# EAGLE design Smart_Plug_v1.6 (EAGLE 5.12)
DIGIKEY: P1.2GCT-ND; HEYCO: 5940; NEWARK: FA-20H, 40MHZ, 10PPM, 12PF; TI: CustomTrans

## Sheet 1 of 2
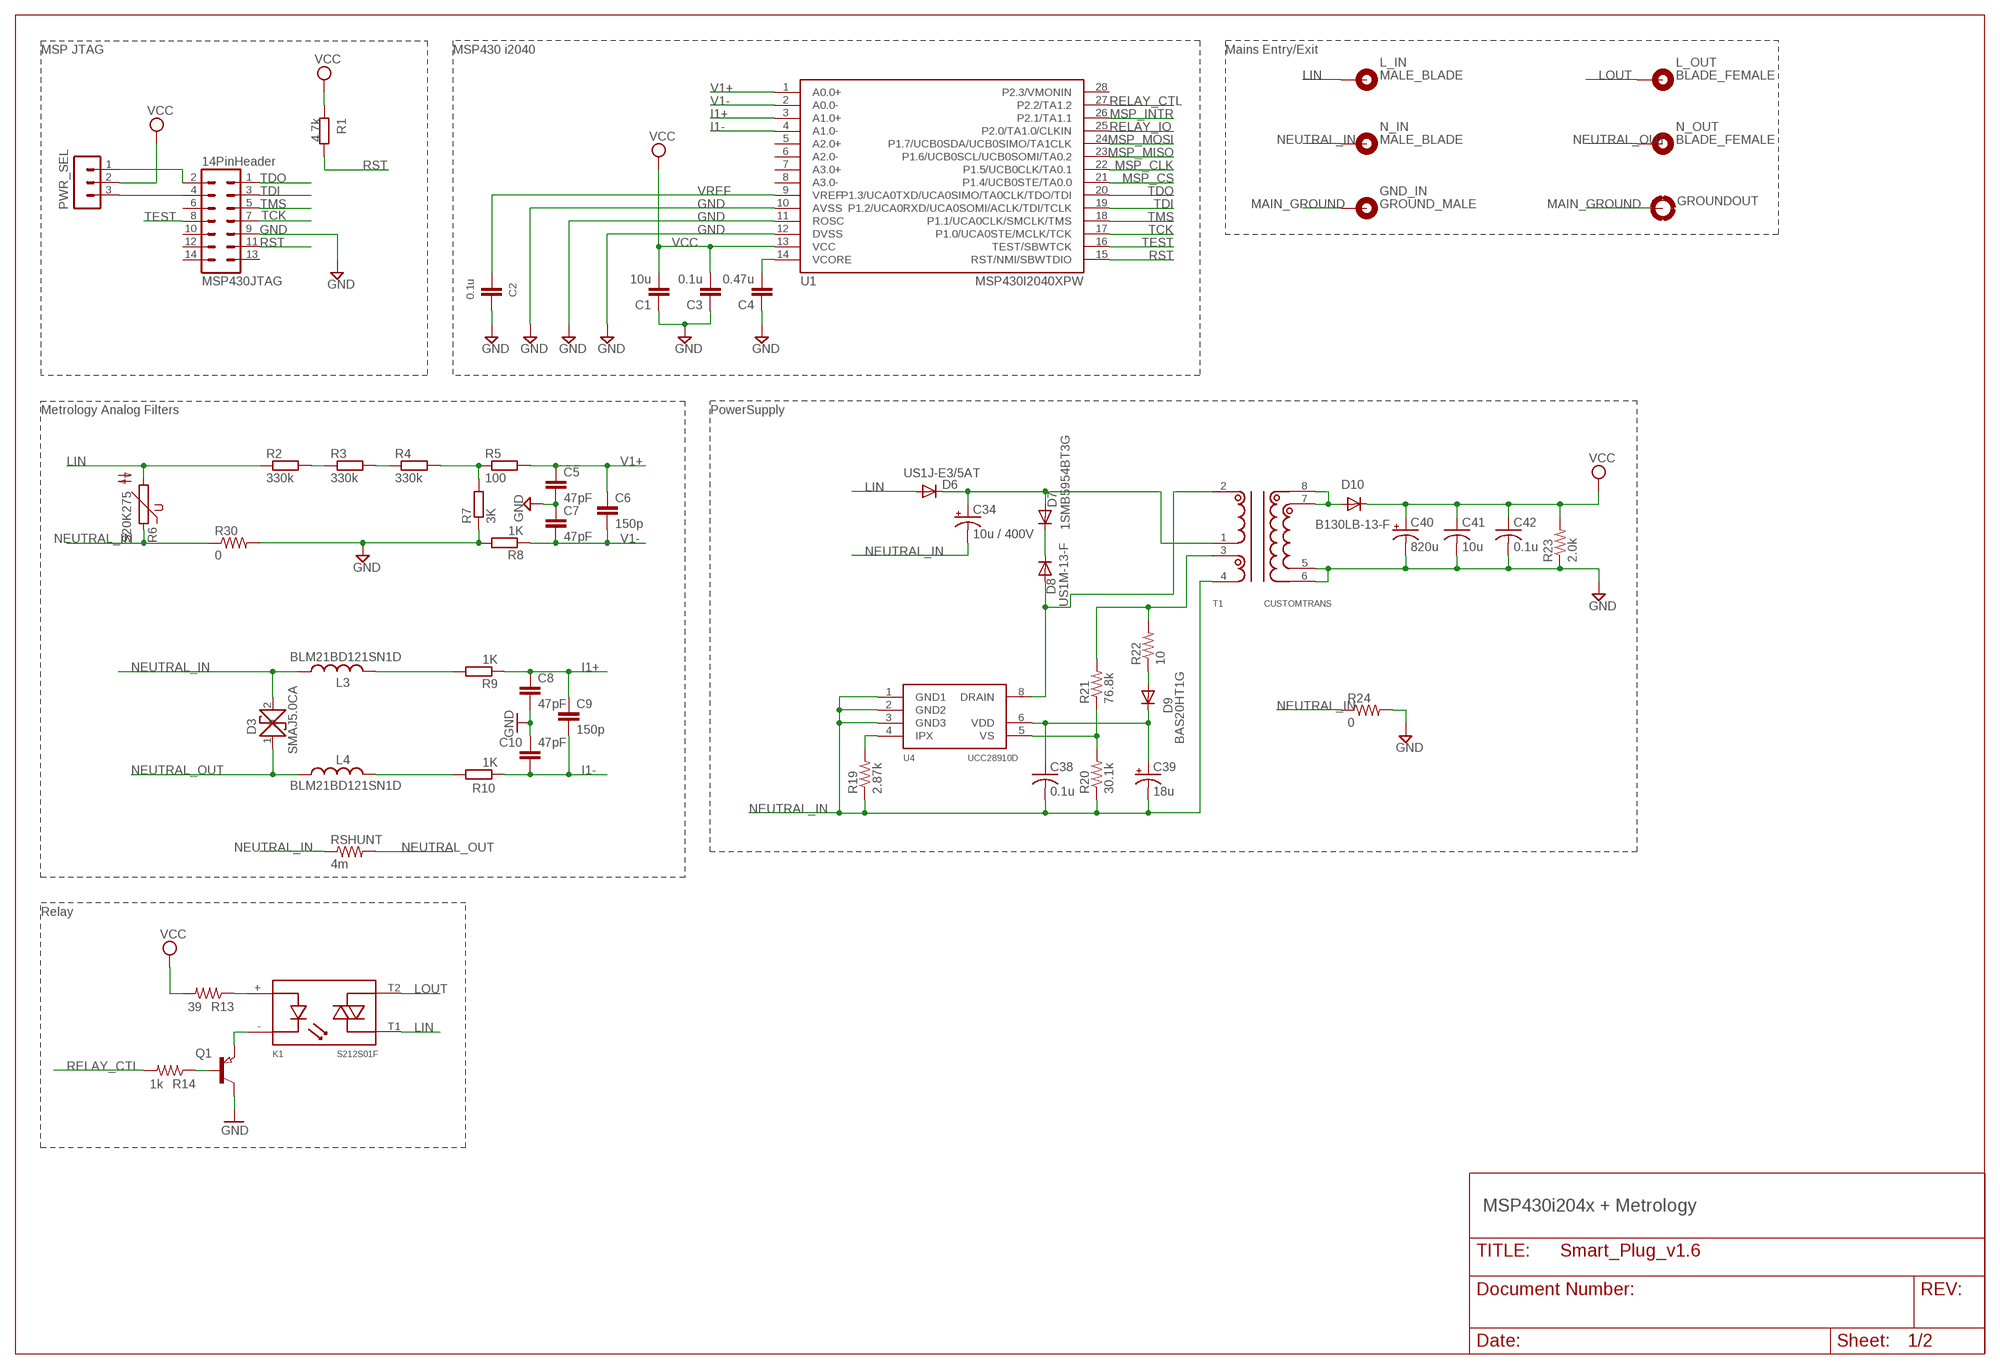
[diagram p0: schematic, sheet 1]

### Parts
C1  10u  C-EUC0603  [C0603]
C2  0.1u  C-EUC0603  [C0603]
C3  0.1u  C-EUC0603  [C0603]
C4  0.47u  C-EUC0603  [C0603]
C5  47pF  C-EUC0603  [C0603]
C6  150p  C-EUC0603  [C0603]
C7  47pF  C-EUC0603  [C0603]
C8  47pF  C-EUC0603  [C0603]
C9  150p  C-EUC0603  [C0603]
C10  47pF  C-EUC0603  [C0603]
C34  10u / 400V  CPOL-USE5-10.5  [E5-10,5]
C38  0.1u  C-USC0603  [C0603]
C39  18u  CPOL-USE5-5  [E5-5]
C40  820u  CPOL-USE3.5-8  [E3,5-8]
C41  10u  C-USC1210  [C1210]
C42  0.1u  C-USC0805  [C0805]
D3  SMAJ5.0CA  SMAJ  [DO-214]
D6  US1J-E3/5AT  DIODE-DO-214AC  [DO-214AC]
D7  1SMB5954BT3G  DIODE-DO-214AC  [DO-214AC]
D8  US1M-13-F  DIODE-DO-214AC  [DO-214AC]
D9  BAS20HT1G  DIODE-SOD323-R  [SOD323-R]
D10  B130LB-13-F  DIODE-DO214AA  [DO214AA]
GND_IN  GROUND_MALE  [GROUND_MALE]
GROUNDOUT  MOUNT-PAD-ROUND3.0  [3,0-PAD]
K1  S212S01F  [S212S01]
L3  BLM21BD121SN1D  L-USL2012C  [L2012C]
L4  BLM21BD121SN1D  L-USL2012C  [L2012C]
L_IN  MALE_BLADE  [BLADE_MALE]
L_OUT  BLADE_FEMALE  [BLADE_FEMALE]
MSP430JTAG  14PinHeader  MA07-2  [MA07-2]
N_IN  MALE_BLADE  [BLADE_MALE]
N_OUT  BLADE_FEMALE  [BLADE_FEMALE]
PWR_SEL  MA03-1MA03-1  [MA03-1]
Q1  PNP-TRANSISTOR_SOT23  [SOT23]
R1  4.7k  R-EU_R0603  [R0603]
R2  330k  R-EU_R0603  [R0603]
R3  330k  R-EU_R0603  [R0603]
R4  330k  R-EU_R0603  [R0603]
R5  100  R-EU_R0603  [R0603]
R6  S20K275  [S20K275]
R7  3K  R-EU_R0603  [R0603]
R8  1K  R-EU_R0603  [R0603]
R9  1K  R-EU_R0603  [R0603]
R10  1K  R-EU_R0603  [R0603]
R13  39  R-US_R0603  [R0603]
R14  1k  R-US_R0603  [R0603]
R19  2.87k  R-US_R0603  [R0603]
R20  30.1k  R-US_R0603  [R0603]
R21  76.8k  R-US_R0603  [R0603]
R22  10  R-US_R0603  [R0603]
R23  2.0k  R-US_R0603  [R0603]
R24  0  R-US_R0805  [R0805]
R30  0  R-US_R0603  [R0603]
RSHUNT  4m  R-US_R4527  [R4527]
T1  CUSTOMTRANS  [TRANS]
U1  MSP430I2040XPW  [TSSOP28]
U4  UCC28910D  [SOIC(D)]

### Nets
DVCC: MSP430JTAG.2 PWR_SEL.1
GND: C1.1 C2.2 C3.1 C4.1 C5.2 C7.1 C8.2 C10.1 C40.- C41.2 C42.2 MSP430JTAG.9 Q1.3(C) R7.1 R8.2 R23.1 R24.2 R30.2 T1.5 T1.6 U1.10(AVSS) U1.11(ROSC) U1.12(DVSS) ; also sheet 2
I1+: C8.1 C9.1 R9.1 U1.3(A1.0+)
I1-: C9.2 C10.2 R10.1 U1.4(A1.0-)
LIN: D6.A K1.T1 L_IN.P$3 R2.1 R6.2
LOUT: K1.T2 L_OUT.P$1
MAIN_GROUND: GND_IN.P$1 GROUNDOUT.B3,0(MOUNT)
MSP_CLK: U1.22(P1.5/UCB0CLK/TA0.1) ; also sheet 2
MSP_CS: U1.21(P1.4/UCB0STE/TA0.0) ; also sheet 2
MSP_INTR: U1.26(P2.1/TA1.1) ; also sheet 2
MSP_MISO: U1.23(P1.6/UCB0SCL/UCB0SOMI/TA0.2) ; also sheet 2
MSP_MOSI: U1.24(P1.7/UCB0SDA/UCB0SIMO/TA1CLK) ; also sheet 2
N$3: L4.2 R10.2
N$4: C34.+ D6.C D7.A T1.1
N$9: K1.+ R13.1
N$10: K1.- Q1.2(E)
N$13: Q1.1(B) R14.1
N$17: D7.C D8.C
N$18: D10.A T1.7 T1.8
N$21: R19.2 U4.4(IPX)
N$22: D8.A T1.2 U4.8(DRAIN)
N$23: C38.1 C39.+ D9.C U4.6(VDD)
N$24: R20.2 R21.1 U4.5(VS)
N$25: D9.A R22.1
N$26: R21.2 R22.2 T1.3
N$32: R4.2 R5.1 R7.2
N$35: C4.2 U1.14(VCORE)
N$39: R2.2 R3.1
N$42: L3.2 R9.2
N$130: MSP430JTAG.4 PWR_SEL.3
NEUTRAL_IN: C34.- C38.2 C39.- D3.2 L3.1 N_IN.P$3 R6.1 R19.1 R20.1 R24.1 R30.1 RSHUNT.1 T1.4 U4.1(GND1) U4.2(GND2) U4.3(GND3)
NEUTRAL_OUT: D3.1 L4.1 N_OUT.P$1 RSHUNT.2
RELAY_CTL: R14.2 U1.27(P2.2/TA1.2)
RELAY_IO: U1.25(P2.0/TA1.0/CLKIN) ; also sheet 2
RST: MSP430JTAG.11 R1.2 U1.15(RST/NMI/SBWTDIO)
TCK: MSP430JTAG.7 U1.17(P1.0/UCA0STE/MCLK/TCK)
TDI: MSP430JTAG.3 U1.19(P1.2/UCA0RXD/UCA0SOMI/ACLK/TDI/TCLK)
TDO: MSP430JTAG.1 U1.20(P1.3/UCA0TXD/UCA0SIMO/TA0CLK/TDO/TDI)
TEST: MSP430JTAG.8 U1.16(TEST/SBWTCK)
TMS: MSP430JTAG.5 U1.18(P1.1/UCA0CLK/SMCLK/TMS)
V1: R3.2 R4.1
V1+: C5.1 C6.1 R5.2 U1.1(A0.0+)
V1-: C6.2 C7.2 R8.1 U1.2(A0.0-)
VCC: C1.2 C3.2 C40.+ C41.1 C42.1 D10.C PWR_SEL.2 R1.1 R13.2 R23.2 U1.13(VCC) ; also sheet 2
VREF: C2.1 U1.9(VREF)
Unconnected: MSP430JTAG.6 MSP430JTAG.10 MSP430JTAG.12 MSP430JTAG.13 MSP430JTAG.14 U1.5(A2.0+) U1.6(A2.0-) U1.7(A3.0+) U1.8(A3.0-) U1.28(P2.3/VMONIN)

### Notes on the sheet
- MSP JTAG | MSP430 i2040 | Mains Entry/Exit
- Metrology Analog Filters | PowerSupply
- Relay
- MSP430i204x + Metrology

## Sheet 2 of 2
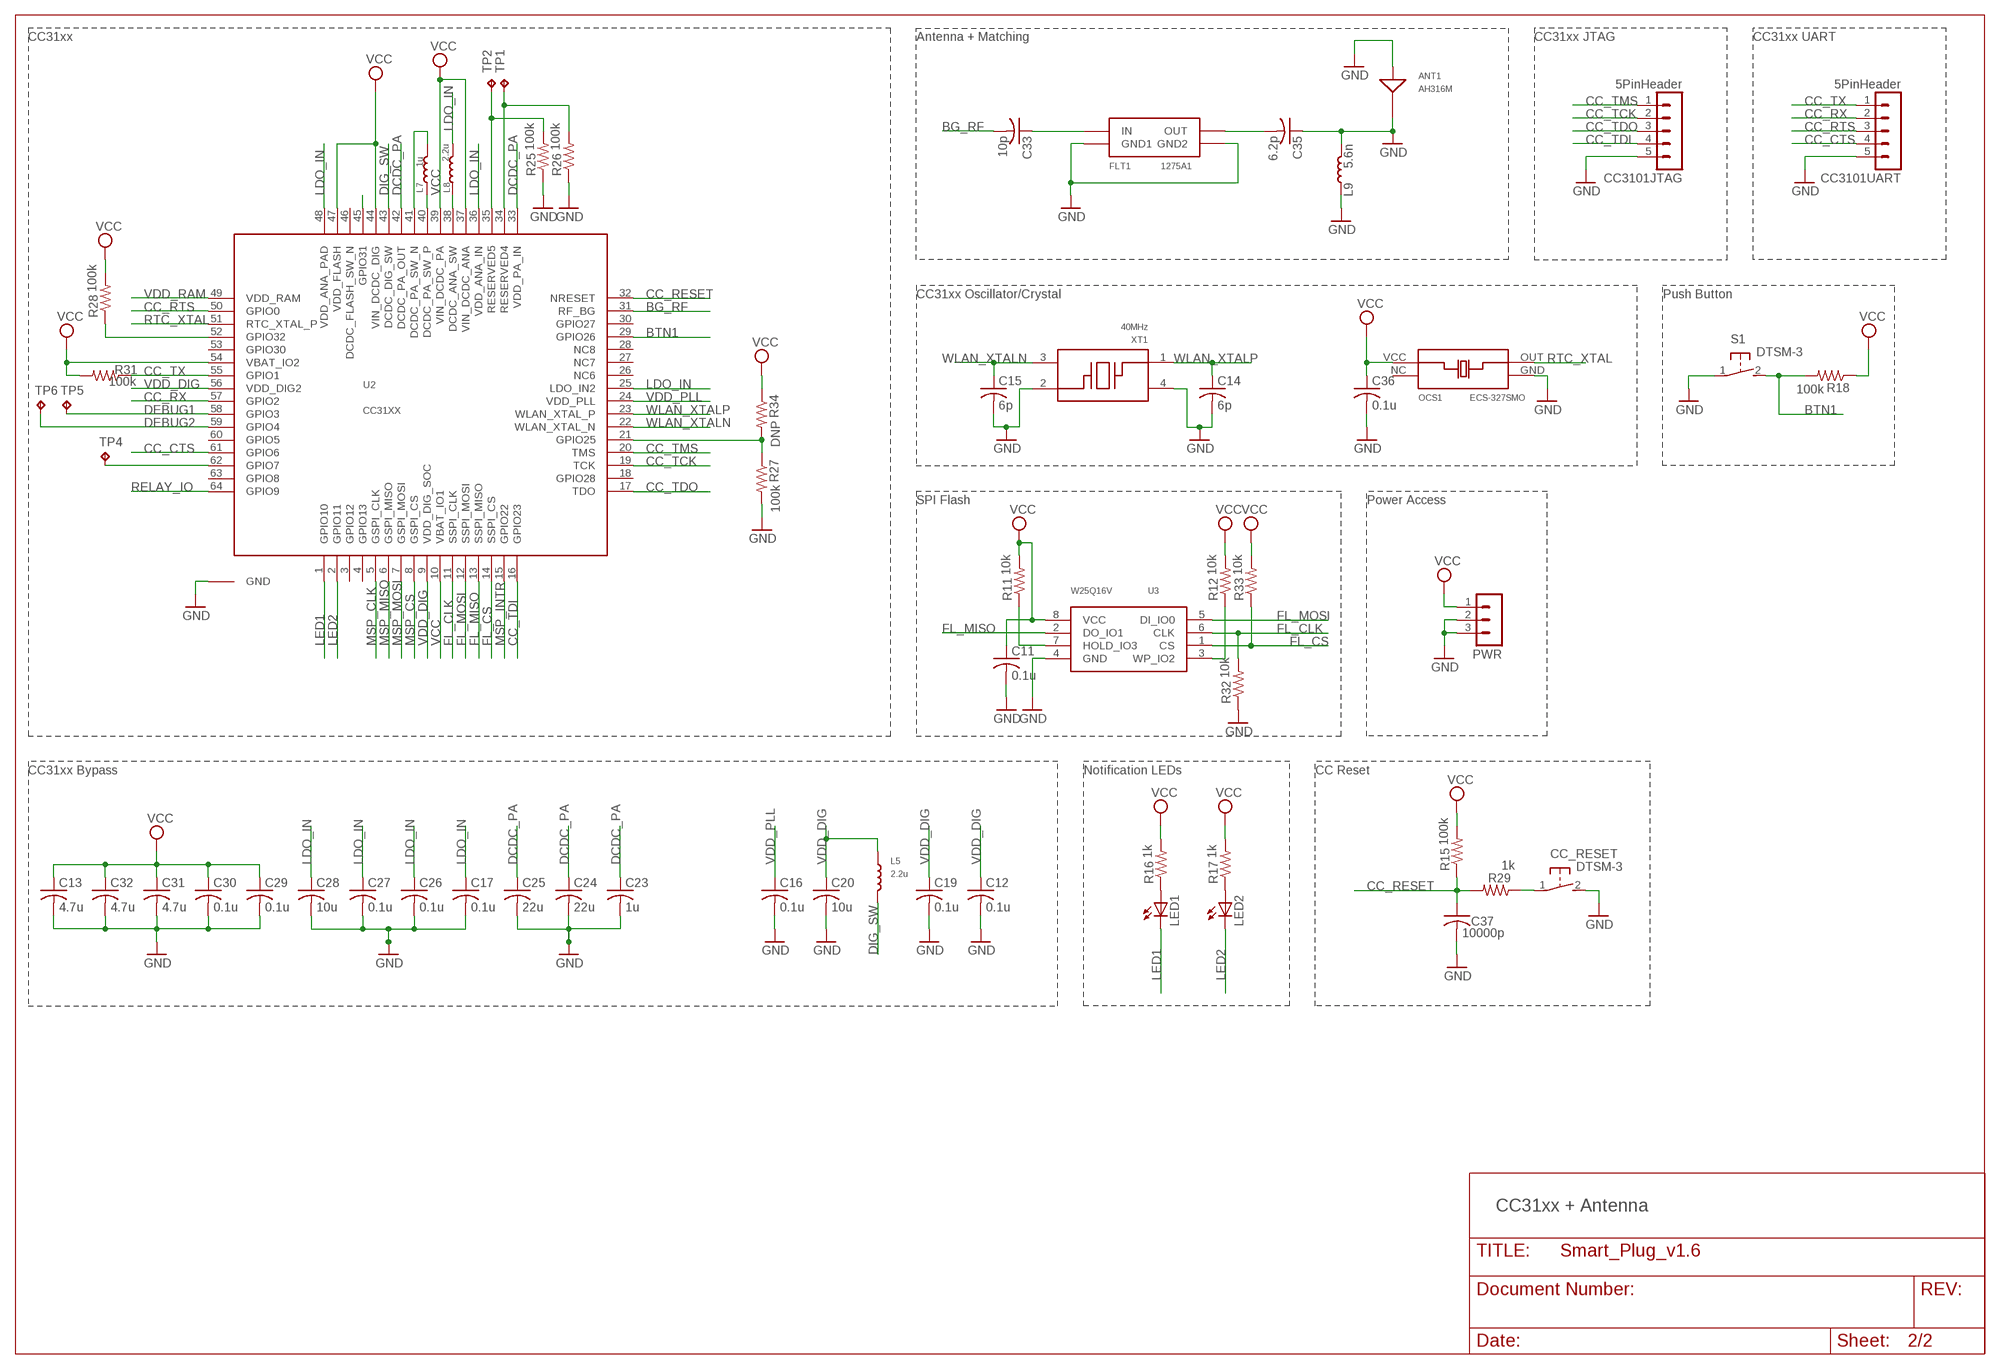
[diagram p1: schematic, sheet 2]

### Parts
ANT1  AH316M  [AH316M]
C11  0.1u  C-USC0402  [C0402]
C12  0.1u  C-USC0201  [C0201]
C13  4.7u  C-USC0402  [C0402]
C14  6p  C-USC0402  [C0402]
C15  6p  C-USC0402  [C0402]
C16  0.1u  C-USC0201  [C0201]
C17  0.1u  C-USC0201  [C0201]
C19  0.1u  C-USC0201  [C0201]
C20  10u  C-USC0402  [C0402]
C23  1u  C-USC0201  [C0201]
C24  22u  C-USC0603  [C0603]
C25  22u  C-USC0603  [C0603]
C26  0.1u  C-USC0201  [C0201]
C27  0.1u  C-USC0402  [C0402]
C28  10u  C-USC0402  [C0402]
C29  0.1u  C-USC0201  [C0201]
C30  0.1u  C-USC0201  [C0201]
C31  4.7u  C-USC0402  [C0402]
C32  4.7u  C-USC0402  [C0402]
C33  10p  C-USC0201  [C0201]
C35  6.2p  C-USC0201  [C0201]
C36  0.1u  C-USC0402  [C0402]
C37  10000p  C-USC0201  [C0201]
CC3101JTAG  5PinHeader  MA05-1  [MA05-1]
CC3101UART  5PinHeader  MA05-1  [MA05-1]
CC_RESET  DTSM-3  [DTSM-3]
FLT1  1275A1  [1275A1]
L5  2.2u  LQM2MPN2R2MG0  [2016]
L7  1u  LQM2HPN1R0MJC  [2520]
L8  2.2u  LQM2MPN2R2MG0  [2016]
L9  5.6n  LQM2HPN1R0MJCL0201  [L0201]
LED1  LEDCHIP-LED0603  [CHIP-LED0603]
LED2  LEDCHIP-LED0603  [CHIP-LED0603]
OCS1  ECS-327SMO  [ECS-327SMO]
PWR  MA03-1  [MA03-1]
R11  10k  R-US_R0402  [R0402]
R12  10k  R-US_R0402  [R0402]
R15  100k  R-US_R0201  [R0201]
R16  1k  R-US_R0402  [R0402]
R17  1k  R-US_R0402  [R0402]
R18  100k  R-US_R0201  [R0201]
R25  100k  R-US_R0201  [R0201]
R26  100k  R-US_R0201  [R0201]
R27  100k  R-US_R0201  [R0201]
R28  100k  R-US_R0201  [R0201]
R29  1k  R-US_R0201  [R0201]
R31  100k  R-US_R0201  [R0201]
R32  10k  R-US_R0201  [R0201]
R33  10k  R-US_R0201  [R0201]
R34  DNP  R-US_R0201  [R0201]
S1  DTSM-3  [DTSM-3]
TP1  TPTP06R  [TP06R]
TP2  TPTP06R  [TP06R]
TP4  TPTP06R  [TP06R]
TP5  TPTP06R  [TP06R]
TP6  TPTP06R  [TP06R]
U2  CC31XX  [S-PVQFN-N64]
U3  W25Q16V  [8PINWSON]
XT1  40MHz  40.0000MF15Z  [FA-20H]

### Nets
ANA2_P: U2.45(GPIO31)
BG_RF: C33.2 U2.31(RF_BG)
BTN1: R18.2 S1.2 U2.29(GPIO26)
CC_CTS: CC3101UART.4 U2.61(GPIO6)
CC_RESET: C37.1 R15.1 R29.2 U2.32(NRESET)
CC_RTS: CC3101UART.3 U2.50(GPIO0)
CC_RX: CC3101UART.2 U2.57(GPIO2)
CC_TCK: CC3101JTAG.2 U2.19(TCK)
CC_TDI: CC3101JTAG.4 U2.16(GPIO23)
CC_TDO: CC3101JTAG.3 U2.17(TDO)
CC_TMS: CC3101JTAG.1 U2.20(TMS)
CC_TX: CC3101UART.1 R31.1 U2.55(GPIO1)
DCDC_PA: C23.1 C24.1 C25.1 U2.33(VDD_PA_IN) U2.42(DCDC_PA_OUT)
DEBUG1: TP5.TP U2.58(GPIO3)
DEBUG2: TP6.TP U2.59(GPIO4)
DIG_SW: L5.P$2 U2.43(DCDC_DIG_SW)
FL_CLK: R32.2 U2.11(SSPI_CLK) U3.6(CLK)
FL_CS: R33.1 U2.14(SSPI_CS) U3.1(CS)
FL_MISO: U2.13(SSPI_MISO) U3.2(DO_IO1)
FL_MOSI: U2.12(SSPI_MOSI) U3.5(DI_IO0)
GND: ANT1.P$1 ANT1.P$2 C11.2 C12.2 C13.2 C14.2 C15.2 C16.2 C17.2 C19.2 C20.2 C23.2 C24.2 C25.2 C26.2 C27.2 C28.2 C29.2 C30.2 C31.2 C32.2 C35.1 C36.2 C37.2 CC3101JTAG.5 CC3101UART.5 CC_RESET.2 FLT1.P$2(GND1) FLT1.P$4(GND2) L9.1 L9.2 OCS1.GND PWR.2 PWR.3 R25.1 R26.1 R27.2 R32.1 S1.1 U2.P$65(GND) U3.4(GND) XT1.2 XT1.4 ; also sheet 1
LDO_IN: C17.1 C26.1 C27.1 C28.1 L8.P$2 U2.25(LDO_IN2) U2.36(VDD_ANA_IN) U2.48(VDD_ANA_PAD)
LED1: LED1.C U2.1(GPIO10)
LED2: LED2.C U2.2(GPIO11)
MSP_CLK: U2.5(GSPI_CLK) ; also sheet 1
MSP_CS: U2.8(GSPI_CS) ; also sheet 1
MSP_INTR: U2.15(GPIO22) ; also sheet 1
MSP_MISO: U2.6(GSPI_MISO) ; also sheet 1
MSP_MOSI: U2.7(GSPI_MOSI) ; also sheet 1
N$1: L7.P$1 U2.40(DCDC_PA_SW_P)
N$2: L7.P$2 U2.41(DCDC_PA_SW_N)
N$5: L8.P$1 U2.38(DCDC_ANA_SW)
N$6: C35.2 FLT1.P$3(OUT)
N$7: R11.1 U3.7(HOLD_IO3)
N$8: R12.1 U3.3(WP_IO2)
N$11: C33.1 FLT1.P$1(IN)
N$12: R25.2 TP2.TP U2.35(RESERVED5)
N$14: R26.2 TP1.TP U2.34(RESERVED4)
N$15: R27.1 R34.2 U2.21(GPIO25)
N$16: TP4.TP U2.62(GPIO7)
N$19: LED1.A R16.1
N$20: LED2.A R17.1
N$30: R28.1 U2.52(GPIO32)
N$31: CC_RESET.1 R29.1
RELAY_IO: U2.64(GPIO9) ; also sheet 1
RTC_XTAL: OCS1.OUT U2.51(RTC_XTAL_P)
VCC: C11.1 C13.1 C29.1 C30.1 C31.1 C32.1 C36.1 OCS1.VCC PWR.1 R11.2 R12.2 R15.2 R16.2 R17.2 R18.1 R28.2 R31.2 R33.2 R34.1 U2.10(VBAT_IO1) U2.37(VIN_DCDC_ANA) U2.39(VIN_DCDC_PA) U2.44(VIN_DCDC_DIG) U2.47(VDD_FLASH) U2.54(VBAT_IO2) U3.8(VCC) ; also sheet 1
VDD_DIG: C12.1 C19.1 C20.1 L5.P$1 U2.9(VDD_DIG_SOC) U2.56(VDD_DIG2)
VDD_PLL: C16.1 U2.24(VDD_PLL)
VDD_RAM: U2.49(VDD_RAM)
WLAN_XTALN: C15.1 U2.22(WLAN_XTAL_N) XT1.3
WLAN_XTALP: C14.1 U2.23(WLAN_XTAL_P) XT1.1
Unconnected: OCS1.NC U2.3(GPIO12) U2.4(GPIO13) U2.18(GPIO28) U2.26(NC6) U2.27(NC7) U2.28(NC8) U2.30(GPIO27) U2.46(DCDC_FLASH_SW_N) U2.53(GPIO30) U2.60(GPIO5) U2.63(GPIO8)

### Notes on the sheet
- CC31xx | Antenna + Matching | CC31xx JTAG | CC31xx UART
- CC31xx Oscillator/Crystal | Push Button
- SPI Flash | Power Access
- CC31xx Bypass | Notification LEDs | CC Reset
- CC31xx + Antenna

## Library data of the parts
ANT1 = Yuden_Ant:AH316M
C1-C7 = resistor:C-EU: CAPACITOR, European symbol
C8-C10 = ElecMeter:C-EU: CAPACITOR, European symbol
C11-C17 C19 C20 C23-C33 C35-C38 C41 C42 = rcl:C-US: CAPACITOR, American symbol
C34 C39 C40 = rcl:CPOL-US: POLARIZED CAPACITOR, American symbol
CC3101JTAG CC3101UART = con-lstb:MA05-1: PIN HEADER; OC_FARNELL: unknown; OC_NEWARK: unknown
CC_RESET S1 = switch-tact:DTSM-3
D3 = CON1:SMAJ
D6-D10 = diode:DIODE-: DIODE
FLT1 = TDK_RF_Filter:1275A1
GND_IN = Heyco_Connectors:GROUND_MALE
GROUNDOUT = holes:MOUNT-PAD-ROUND: MOUNTING PAD, round
K1 = Sharp_SSR:S212S01F
L3 L4 = ElecMeter:L-US: INDUCTOR, American symbol
L5 L8 = MurataInductors:LQM2MPN2R2MG0
L7 L9 = MurataInductors:LQM2HPN1R0MJC
L_IN N_IN = Heyco_Connectors:MALE_BLADE
L_OUT N_OUT = Heyco_Connectors:BLADE_FEMALE
LED1 LED2 = led:LED: LED
MSP430JTAG = partsElecMeter_i4020Mod:MA07-2: PIN HEADER
OCS1 = ECS_OSC:ECS-327SMO
PWR = con-lstb:MA03-1: PIN HEADER; OC_FARNELL: unknown; OC_NEWARK: unknown
PWR_SEL = ElecMeter:MA03-1: PIN HEADER
Q1 = semicon-smd-ipc:PNP-TRANSISTOR_: PNP TRANSISTOR
R1-R5 R7-R10 = ElecMeter:R-EU_: RESISTOR, European symbol
R6 = varistor:S20K275: VARISTOR
R11-R34 RSHUNT = rcl:R-US_: RESISTOR, American symbol
T1 = RencoTransformer:CUSTOMTRANS
TP1 TP2 TP4-TP6 = testpad:TP: Test pad
U1 = MSP430i204x:MSP430I2040XPW
U2 = CC31xx:CC31XX
U3 = W25Q16V:W25Q16V
U4 = UCC28910:UCC28910D
XT1 = Epson Crystals:40.0000MF15Z

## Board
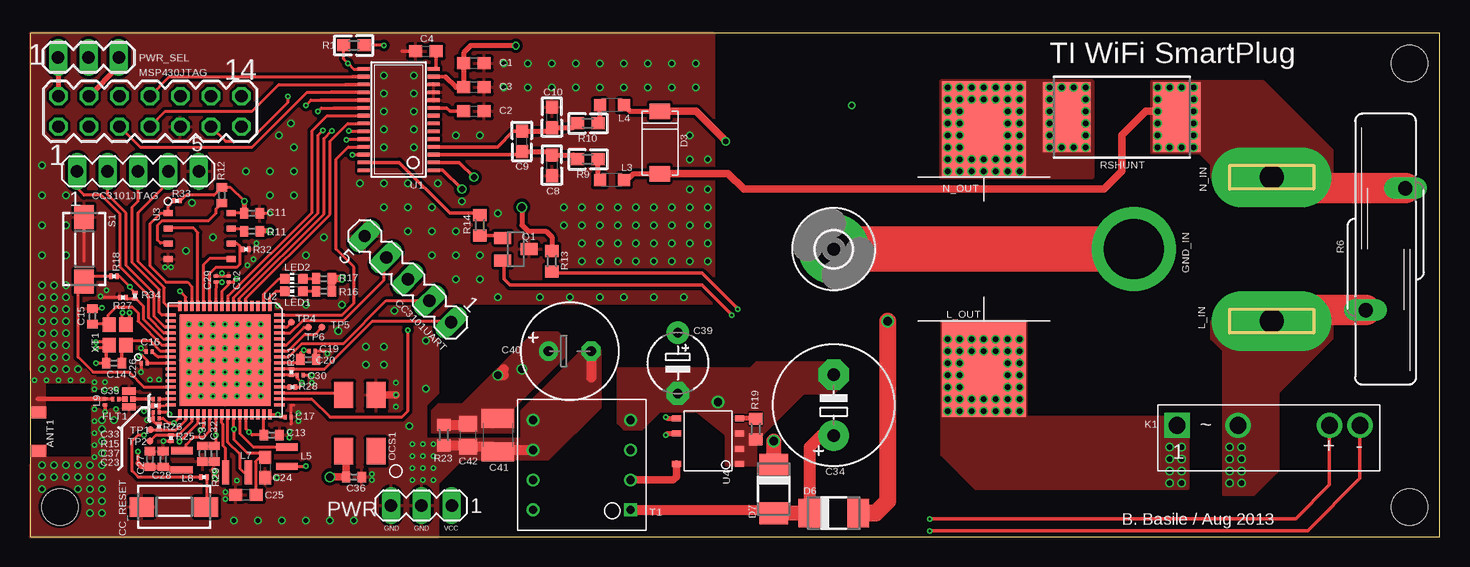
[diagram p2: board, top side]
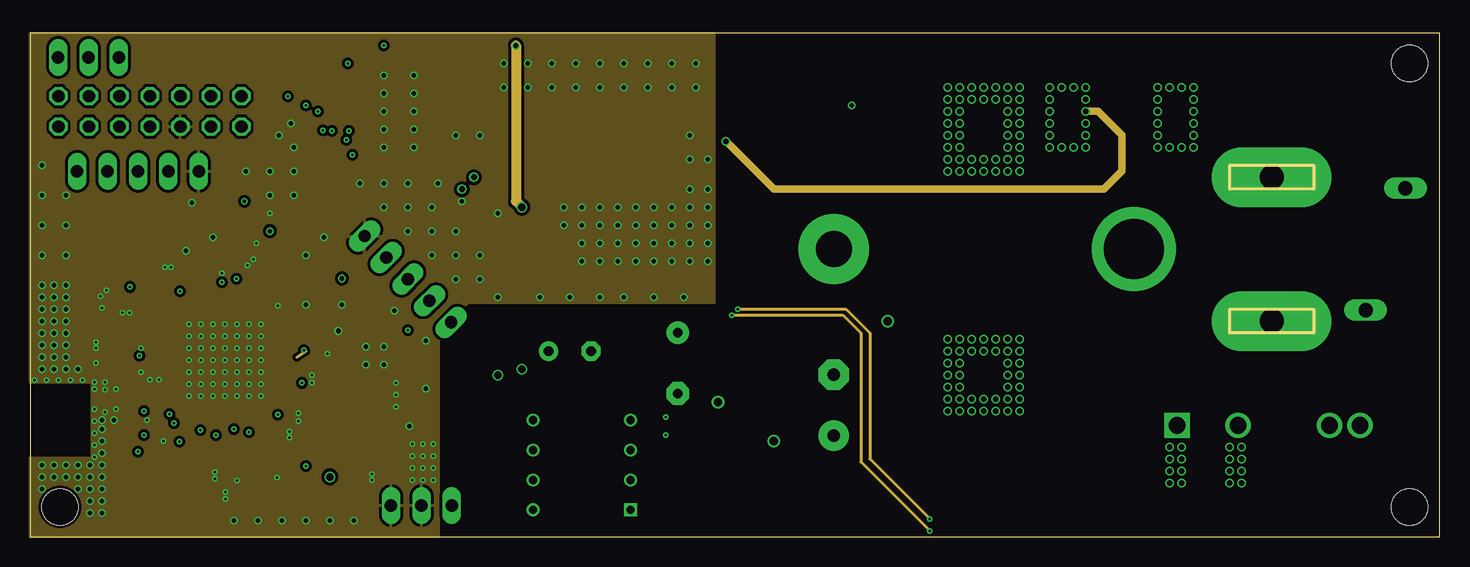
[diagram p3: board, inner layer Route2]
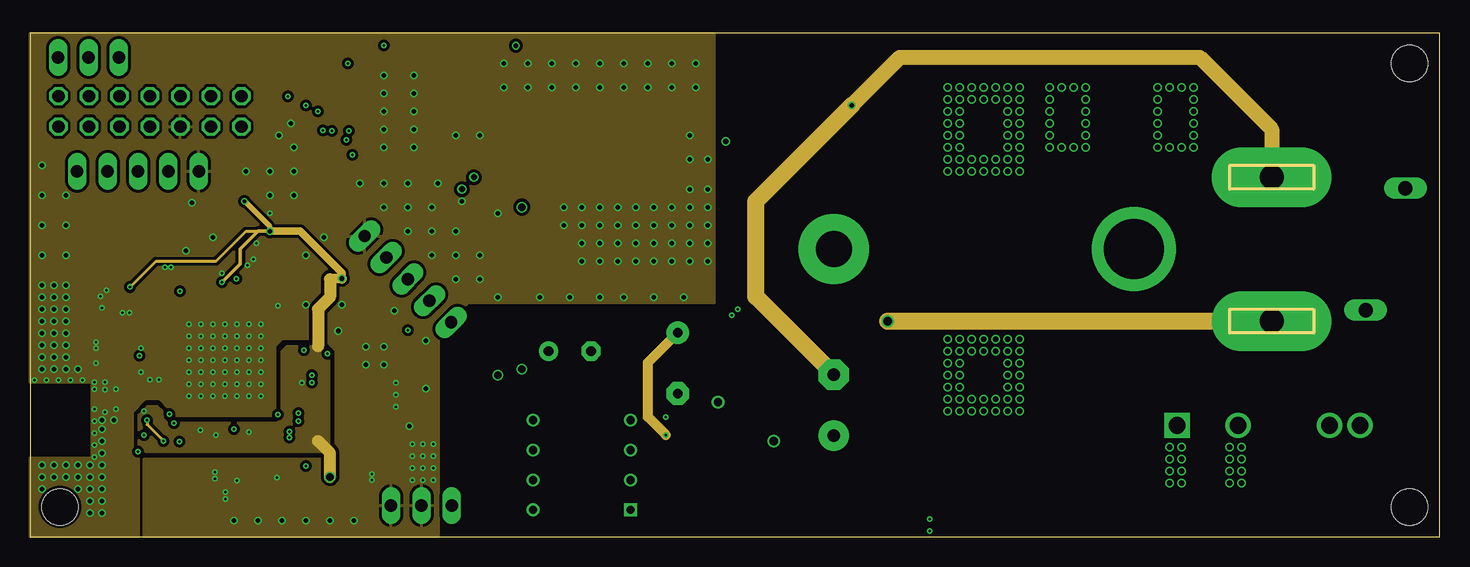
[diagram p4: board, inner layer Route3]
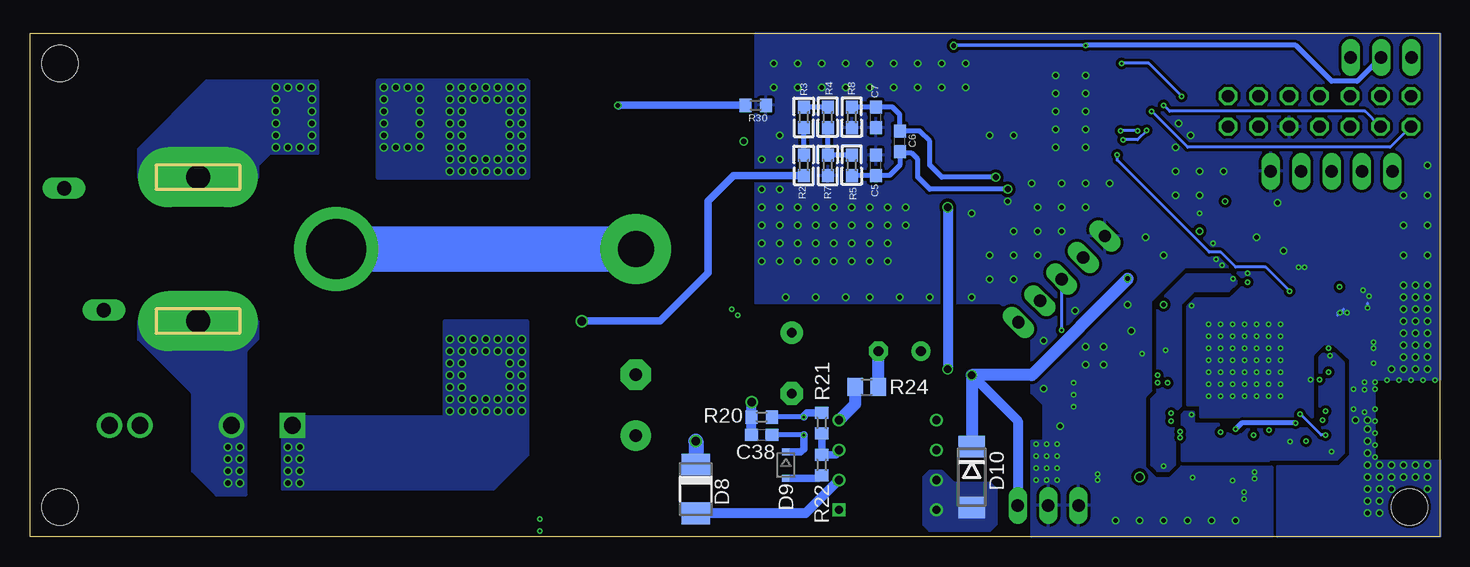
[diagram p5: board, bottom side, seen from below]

Size 117.5 x 42 mm. Coordinates in mm from the lower left corner, seen from the top.
Outline: 0,0 117.5,0 117.5,42 0,42 0,0
Copper layers (1*2*3*16): Top 0.035mm / dielectric 0.2032mm / Route2 0.035mm / dielectric 1.016mm / Route3 0.035mm / dielectric 0.2032mm / Bottom 0.035mm
Design rules "typical_4pcb_4layer *": minimum track width 5mil, minimum drill 4mil, track to track 5mil, track to pad 5mil, pad to pad 5mil, via to via 5mil, smd to smd 0.0699mm, copper to edge 0mil, drill to drill 6mil, minimum pad ring 5mil, minimum via ring 5mil, stop-mask expansion 1mil, vias tented up to drill 25mil, thermal gap 10mil
Holes 3 mm at 115,39.5 115,2.5 2.5,2.5
tRestrict: area 5,14 to 8.5,19.5; area 4.5,11 to 7.5,12
bRestrict: area 0,6.7 to 5.1,12.8

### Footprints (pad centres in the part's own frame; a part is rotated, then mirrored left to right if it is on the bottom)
AH316M = smd 1 x 1.2: P$1 1.6,0; P$2 -1.6,0
C0603 = smd 1.1 x 1: 1 -0.85,0; 2 0.85,0
C0402 = smd 0.7 x 0.9: 1 -0.65,0; 2 0.65,0
C0201 = smd 0.25 x 0.35: 1 -0.25,0; 2 0.25,0
E5-10,5 = drill 1.016 pad 2.54 round: + -2.54,0 | drill 1.016 pad 2.54 octagon: - 2.54,0
E5-5 = drill 0.813 pad 1.905 round: + -2.54,0 | drill 0.813 pad 1.905 octagon: - 2.54,0
E3,5-8 = drill 0.813 pad 1.6 round: + -1.778,0 | drill 0.813 pad 1.6 octagon: - 1.778,0
C1210 = smd 1.6 x 2.7: 1 -1.4,0; 2 1.4,0
C0805 = smd 1.3 x 1.5: 1 -0.95,0; 2 0.95,0
MA05-1 = drill 1.016 long: 1 -5.08,0; 2 -2.54,0; 3 0,0; 4 2.54,0; 5 5.08,0
DTSM-3 = smd 2 x 1.6: 1 -2.7,0; 2 2.7,0
DO-214 = smd 1.3 x 1.7: 1 0,0; 2 5.2,0
DO-214AC = smd 1.8 x 2.4: A 2.025,0; C -2.025,0
SOD323-R = smd 0.6 x 0.6: A 1.1,0; C -1.1,0
DO214AA = smd 1.8 x 2.2: A 2.55,0; C -2.55,0
1275A1 = smd 0.45 x 0.45: P$1 -0.325,0; P$3 0.325,0 | smd 1.1 x 0.55: P$2 0,-0.65; P$4 0,0.65
GROUND_MALE = drill 5 pad 7 round: P$1 0,0
3,0-PAD = drill 3 pad 5.842 round: B3,0 0,0
S212S01 = drill 1.4 round: + 14.33,3.8; - 16.87,3.8; T1 6.71,3.8 | drill 1.4 square: T2 1.63,3.8
L2012C = smd 1 x 1: 1 -1,0; 2 1,0
2016 = smd 0.6 x 1.8: P$1 -0.8,0; P$2 0.8,0
2520 = smd 0.6 x 2: P$1 -0.95,0; P$2 0.95,0
L0201 = smd 0.25 x 0.35: 1 -0.25,0; 2 0.25,0
BLADE_MALE = drill 2 pad 5 long: P$3 0,0
BLADE_FEMALE = smd 7 x 8: P$1 0,-4
CHIP-LED0603 = smd 0.8 x 0.8: A 0,-0.75; C 0,0.75
MA07-2 = drill 1.016 octagon: 1 -7.62,-1.27; 2 -7.62,1.27; 3 -5.08,-1.27; 4 -5.08,1.27; 5 -2.54,-1.27; 6 -2.54,1.27; 7 0,-1.27; 8 0,1.27; 9 2.54,-1.27; 10 2.54,1.27; 11 5.08,-1.27; 12 5.08,1.27; 13 7.62,-1.27; 14 7.62,1.27
ECS-327SMO = smd 2.2 x 1.6: GND 2.35,-1.35; NC -2.35,-1.35; OUT 2.35,1.35; VCC -2.35,1.35
MA03-1 = drill 1.016 long: 1 -2.54,0; 2 0,0; 3 2.54,0
SOT23 = smd 1 x 1.4: 1 -0.95,-1.1; 2 0.95,-1.1; 3 0,1.1
R0603 = smd 1.1 x 1: 1 -0.85,0; 2 0.85,0
S20K275 = drill 1.194 long: 1 -1.651,-5.08; 2 1.651,5.08
R0402 = smd 0.7 x 0.9: 1 -0.65,0; 2 0.65,0
R0603' = smd 1 x 1.1: 1 -0.85,0; 2 0.85,0
R0201 = smd 0.28 x 0.43: 1 -0.255,0; 2 0.255,0
R0805 = smd 1.3 x 1.5: 1 -0.95,0; 2 0.95,0
R4527 = smd 3.94 x 5.84: 1 -4.575,0; 2 4.575,0
TRANS = drill 0.7 square: 1 -3.734,-4.064 | drill 0.7 round: 2 -1.245,-4.064; 3 1.245,-4.064; 4 3.734,-4.064; 5 3.734,4.064; 6 1.245,4.064; 7 -1.245,4.064; 8 -3.734,4.064
TP06R = smd 0.6 x 0.6: TP 0,0
TSSOP28 = smd 0.305 x 0.991: 1 -0.415,-1.648; 2 0.235,-1.648; 3 0.885,-1.648; 4 1.535,-1.648; 5 2.185,-1.648; 6 2.835,-1.648; 7 3.485,-1.648; 8 4.135,-1.648; 9 4.785,-1.648; 10 5.435,-1.648; 11 6.085,-1.648; 12 6.735,-1.648; 13 7.385,-1.648; 14 8.035,-1.648; 15 8.035,4.188; 16 7.385,4.188; 17 6.735,4.188; 18 6.085,4.188; 19 5.435,4.188; 20 4.785,4.188; 21 4.135,4.188; 22 3.485,4.188; 23 2.835,4.188; 24 2.185,4.188; 25 1.535,4.188; 26 0.885,4.188; 27 0.235,4.188; 28 -0.415,4.188
S-PVQFN-N64 = smd 0.28 x 0.85: 1 1.01,0.235; 2 1.51,0.235; 3 2.01,0.235; 4 2.51,0.235; 5 3.01,0.235; 6 3.51,0.235; 7 4.01,0.235; 8 4.51,0.235; 9 5.01,0.235; 10 5.51,0.235; 11 6.01,0.235; 12 6.51,0.235; 13 7.01,0.235; 14 7.51,0.235; 15 8.01,0.235; 16 8.51,0.235; 33 8.51,9.285; 34 8.01,9.285; 35 7.51,9.285; 36 7.01,9.285; 37 6.51,9.285; 38 6.01,9.285; 39 5.51,9.285; 40 5.01,9.285; 41 4.51,9.285; 42 4.01,9.285; 43 3.51,9.285; 44 3.01,9.285; 45 2.51,9.285; 46 2.01,9.285; 47 1.51,9.285; 48 1.01,9.285 | smd 0.85 x 0.28: 17 9.265,0.99; 18 9.265,1.49; 19 9.265,1.99; 20 9.265,2.49; 21 9.265,2.99; 22 9.265,3.49; 23 9.265,3.99; 24 9.265,4.49; 25 9.265,4.99; 26 9.265,5.49; 27 9.265,5.99; 28 9.265,6.49; 29 9.265,6.99; 30 9.265,7.49; 31 9.265,7.99; 32 9.265,8.49; 49 0.215,8.49; 50 0.215,7.99; 51 0.215,7.49; 52 0.215,6.99; 53 0.215,6.49; 54 0.215,5.99; 55 0.215,5.49; 56 0.215,4.99; 57 0.215,4.49; 58 0.215,3.99; 59 0.215,3.49; 60 0.215,2.99; 61 0.215,2.49; 62 0.215,1.99; 63 0.215,1.49; 64 0.215,0.99 | smd 7.6 x 7.6: P$65 4.74,4.76
8PINWSON = smd 0.5 x 0.75: 1 0,1; 2 1.27,1; 3 2.54,1; 4 3.81,1; 5 3.81,6.25; 6 2.54,6.25; 7 1.27,6.25; 8 0,6.25
SOIC(D) = smd 0.5 x 0.75: 1 -1.905,-2.625; 2 -0.635,-2.625; 3 0.635,-2.625; 4 1.905,-2.625; 5 1.9,2.625; 6 0.635,2.625; 8 -1.905,2.625
FA-20H = smd 1.2 x 1.1: 1 1,1; 2 2.7,1; 3 2.7,2.4; 4 1,2.4

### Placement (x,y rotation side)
ANT1  0.75,8.8 270 top
C1  37,39.5 180 top
C2  37,35.5 0 top
C3  37,37.5 180 top
C4  33,40.5 0 top
C5  47,31 90 bottom
C6  45,33 90 bottom
C7  47,35 90 bottom
C8  43.5,31 270 top
C9  41,33 90 top
C10  43.5,35 270 top
C11  18.5,27 0 top
C12  16.55,21.5 90 top
C13  20.15,8.5 0 top
C14  7,14.5 180 top
C15  5.2,18.4 90 top
C16  9.95,15.45 180 top
C17  21.5,10 0 top
C19  23.5,15.5 0 top
C20  23.2,14.8 0 top
C23  10.5,9.9 180 top
C24  19.6,5.8 270 top
C25  18,3.5 180 top
C26  9.5,14.5 180 top
C27  10,6.5 90 top
C28  11.1,6.5 90 top
C29  15.5,21.5 90 top
C30  22.5,13.5 0 top
C31  14.38,6.95 270 top
C32  15.35,6.95 270 top
C33  10.5,11.5 0 top
C34  67,11 90 top
C35  7.12,11.5 0 top
C36  27,5 0 top
C37  10.5,10.4 180 top
C38  56.5,8.5 180 bottom
C39  54,14.5 270 top
C40  45,15.5 0 top
C41  39,8.5 270 top
C42  36.5,8.5 270 top
CC3101JTAG  9,30.5 0 top
CC3101UART  31.5,21.5 135 top
CC_RESET  12,2.5 180 top
D3  52.5,35.5 270 top
D6  67,2 0 top
D7  62,4 270 top
D8  62,4 270 bottom
D9  54.5,6 270 bottom
D10  39,5 270 bottom
DRILEGEND  [DRILEGEND]  not placed on the board
FLT1  8.25,11.5 180 top
GND_IN  92,24 270 top
GROUNDOUT  67,24 270 top
K1  94,5.5 0 top
L3  48.5,29.75 180 top
L4  48.5,36 180 top
L5  21.4,6.7 90 top
L7  17.25,5.4 0 top
L8  12.65,6.4 270 top
L9  6.25,11.25 90 top
L_IN  103.5,18 270 top
L_OUT  79.5,18 0 top
LED1  22,20.5 90 top
LED2  22,21.55 90 top
MSP430JTAG  10,35.5 0 top
N_IN  103.5,30 270 top
N_OUT  79.5,30 180 top
OCS1  27.5,9.5 90 top
PWR  32.62,2.62 180 top
PWR_SEL  4.88,40 0 top
Q1  40.5,24 270 top
R1  27,41 180 top
R2  53,31 90 bottom
R3  53,35 90 bottom
R4  51,35 270 bottom
R5  49,31 270 bottom
R6  113,24 180 top
R7  51,31 90 bottom
R8  49,35 270 bottom
R9  46.5,31.5 0 top
R10  46.5,34.5 0 top
R11  18.5,25.5 0 top
R12  16,28.5 90 top
R13  39  [R0603']  43.5,23 90 top
R14  1k  [R0603']  37.5,26 90 top
R15  10.5,10.95 180 top
R16  24.5,20.5 0 top
R17  24.5,21.55 0 top
R18  7,21.75 180 top
R19  2.87k  [R0603']  60.5,9 90 top
R20  30.1k  [R0603']  56.5,10 0 bottom
R21  76.8k  [R0603']  51.5,9.5 270 bottom
R22  10  [R0603']  51.5,6 90 bottom
R23  2.0k  [R0603']  34.5,8.5 90 top
R24  47.75,12.5 0 bottom
R25  11.75,8.25 90 top
R26  10.75,9.2 270 top
R27  7.75,19.98 180 top
R28  21.88,12.5 0 top
R29  14.5,5 180 top
R30  0  [R0603']  57,36 0 bottom
R31  21.8,13.75 270 top
R32  18,24 180 top
R33  12.25,28.05 0 top
R34  8.75,20.1 270 top
RSHUNT  91,35 180 top
S1  4.5,24 270 top
T1  46,6 90 top
TP1  10.05,8.95 0 top
TP2  10,8 0 top
TP4  21.77,17.9 0 top
TP5  24.32,17.48 0 top
TP6  23.2,17.48 0 top
U1  32,31 90 top
U2  21,19.5 180 top
U3  10.5,27 270 top
U4  56.5,8 90 top
XT1  9,15 90 top

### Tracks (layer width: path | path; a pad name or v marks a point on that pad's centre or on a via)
BG_RF
  Top 0.254: U2.31 C33.2
BTN1
  Top 0.254: U2.29 9.49,12.51 8.25,13.75 5.25,13.75 4,15 4,20.8 S1.2 | S1.2 4.55,21.25 | R18.2 4.5,21.75 S1.2
CC_CTS
  Top 0.254: CC3101UART.4 29.5,23.09 29.5,21.43 26.15,18.07 22.75,18.07 21.68,17.01 U2.61
CC_RESET  (via drill 0.2)
  Top 0.254: U2.32 R15.1 | 10.75,10.99 C37.1 11.47,10.4 v11.62,10.25 | v9.5,8.5 9,8.5 8.5,8 8.5,5.5 9,5 R29.2
  Top 0.305: 10.75,10.99 10.76,10.99 R15.1
  Bottom 0.254: v11.62,10.25 9.88,8.5 v9.5,8.5
CC_RTS  (via drill 0.2)
  Top 0.254: U2.50 23.49,11.51 25,10 31,10 31.5,10.5 v31.5,17.25
  Bottom 0.254: v31.5,17.25 CC3101UART.3
CC_RX
  Top 0.254: U2.57 21.55,15 22.68,16.12 26.12,16.12 29.7,19.7 CC3101UART.2
CC_TCK
  Top 0.254: U2.19 11.24,17.51 10.35,18.4 10.35,20.3 8,22.65 8,27 6.46,28.54 CC3101JTAG.2
CC_TDI
  Top 0.254: 12.5,19.5 U2.16 11.44,19.27 11.2,19.5 11.2,20.8 9.04,22.96 9.04,27.04 11.54,29.54 CC3101JTAG.4
CC_TDO
  Top 0.254: U2.17 10.99,18.51 10.78,18.73 10.78,20.62 8.5,22.9 8.5,27.5 9,28 CC3101JTAG.3
CC_TMS
  Top 0.254: U2.20 11.16,17.01 9.88,18.3 9.88,20.12 7.5,22.5 7.5,26.95 5.95,28.5 4.5,28.5 3.92,29.08 CC3101JTAG.1
CC_TX
  Top 0.254: 21.5,14.01 U2.55 | 21.5,14.01 24.56,14.01 28.55,18 35,18 CC3101UART.1 | R31.1 21.5,14.01
DCDC_PA  (via drill 0.2)
  Top 0.254: U2.42 v16.99,9 16.99,8.12 18.11,7 19.6,7 C24.1 | 12.49,10 U2.33 12.49,9.99 v12,9.5 11.5,9.5 11.1,9.9 C23.1 | C25.1 18.8,3.6 18.8,6.3 19,6.5 19.45,6.5 C24.1 | C24.1 19.6,6.5
  Bottom 0.254: v16.99,9.01 v16.99,9
  Bottom 0.406: v16.99,9.01 16.5,9.5 v12,9.5
DEBUG1
  Top 0.254: U2.58 21.51,15.51 22.9,16.9 23.75,16.9 TP5.TP
DEBUG2
  Top 0.254: U2.59 21.39,16.01 22.85,17.48 TP6.TP
DIG_SW
  Top 0.254: U2.43 17.5,8.62 18.62,7.5 L5.P$2
DVCC
  Top 0.406: PWR_SEL.1 2.38,39.95 MSP430JTAG.2
FL_CLK
  Top 0.254: U2.11 14.99,21.99 15.5,22.5 17.25,22.5 17.5,22.75 17.5,24 | U3.6 17.29,24.46 17.5,24.25 17.5,24 | 17.5,24 R32.2
FL_CS
  Top 0.254: U2.14 13.49,20.89 13.12,21.25 11.35,21.25 10,22.6 10,26.12 10.88,27 U3.1 11.5,27.55 R33.1
FL_MISO
  Top 0.254: U2.13 13.99,25.39 13.62,25.75 11.52,25.75 U3.2
FL_MOSI
  Top 0.254: U2.12 14.49,22.74 15,23.25 16.69,23.25 U3.5
GND  (via drill 0.2, 0.4)
  Top 0.254: C30.2 v23.5,13.5 | C16.2 v9.25,15.75 | C11.2 v20,27 | C29.2 16,21.75 | 16,21.75 C12.2 | 16,21.75 v16,22 | 4.5,23 S1.1 | R25.1 v11.13,8 v11.12,8 | C23.2 C37.2 | C23.2 9.95,9.9 v9.75,9.75 | C23.2 10.25,9.7 10.49,9.46 R26.1 | v5.5,14.5 6.5,14.5 | v5.5,16.25 6.6,16.25 XT1.4 | v5.5,15.75 6.5,15.75 6.5,16 | 0.65,11.5 0.62,11.5 | C26.2 v9.25,13.75 | C15.2 5.95,19.05 v6,19.1 | v8.3,18.7 8.3,17.9 8.2,17.9 XT1.2 8,17.5 7.7,17.5 v7.7,18.7 | C19.2 24.6,15.5 v24.8,15.3 | 15.4,5.5 15.2,5.7 | 21.75,9.4 C17.2 21.75,11 22,11 | R27.2 5.97,19.98 v5.88,20.07
  Top 0.305: C14.2 6.35,16 6.5,16 XT1.4 | C4.1 31,40.5 | L9.2 C35.1 | L9.1 v6.25,10.43
  Top 0.381: 0.65,11.5 L9.2
  Top 0.406: U2.P$65 v16.25,14.75 | 15.4,4.8 15.4,5.5
  Top 0.61: OCS1.GND v30.5,11.85
  Top 0.813: C40.- 46.78,13.27 | T1.6 39.15,7.25 C41.2 38.55,7.55 C42.2 36.4,7.65 R23.1
  Route3 0.254: v11.12,8 9.75,9.38 v9.75,9.75
  Bottom 0.254: v6,19.1 6,19.5 | v8.3,18.7 8,19 | v7.7,18.7 8.5,18.7 8.5,18.5
  Bottom 1.016: R24.2 46.78,12.5 C40.-
  other vias: 16.3,3.75 28.5,4.75 11.25,22.5 45.5,39.5 19.25,17.75 18.25,17.75 17.25,17.75 16.25,17.75 15.25,17.75 14.25,17.75 13.25,17.75 19.25,16.75 18.25,16.75 17.25,16.75 16.25,16.75 15.25,16.75 14.25,16.75 13.25,16.75 13.25,15.75 14.25,15.75 15.25,15.75 16.25,15.75 17.25,15.75 18.25,15.75 19.25,15.75 19.25,14.75 18.25,14.75 17.25,14.75 15.25,14.75 14.25,14.75 13.25,14.75 13.25,13.75 14.25,13.75 15.25,13.75 16.25,13.75 17.25,13.75 18.25,13.75 19.25,13.75 19.25,12.75 18.25,12.75 17.25,12.75 16.25,12.75 15.25,12.75 14.25,12.75 13.25,12.75 13.25,11.75 14.25,11.75 15.25,11.75 16.25,11.75 17.25,11.75 18.25,11.75 19.25,11.75 31.88,7.75 31.88,6.75 31.88,5.75 31.88,4.75 32.75,4.75 32.75,5.75 32.75,6.75 32.75,7.75 33.62,7.75 33.62,6.75 33.62,5.75 33.62,4.75 27.5,29.5 29.5,29.5 31.5,29.5 29.5,27.5 31.5,27.5 31.5,25.5 33.5,25.5 33.5,27.5 33.5,23.5 35.5,23.5 35.5,25.5 41.5,39.5 41.5,37.5 39.5,39.5 39.5,37.5 43.5,39.5 43.5,37.5 45.5,37.5 47.5,39.5 49.5,39.5 51.5,39.5 51.5,37.5 49.5,37.5 47.5,37.5 53.5,39.5 55.5,39.5 1,14 1,15 1,16 1,17 1,18 1,19 1,20 1,21 2,21 2,20 2,19 2,18 2,17 2,16 2,15 2,14 3,14 3,15 3,16 3,17 3,18 3,19 3,20 3,21 4,14 6,7 6,6 5,6 4,6 3,6 2,6 1,6 1,5 2,5 3,5 4,5 5,5 6,5 1,4 5,4 6,4 5,3 6,3 6,8 6,9 6,9.75 7,9.75 56.5,31.5 55,31.5 55,33.5 56.5,29 36,28 37.5,33.5 35.5,33.5 53.5,37.5 34,29.5 5.38,12.32 35.5,21.5 37.5,21.5 37.5,23.5 39,27 39,20 42.5,20 45,20 47.5,20 49.5,20 52,20 54.5,20 29.5,32.5 29.5,34 29.5,35.5 29.5,37 32,37 32,35.5 32,34 32,32.5 29.5,38.5 32,38.5 4,4 24.5,25 23,23.5 26,19.38 23,19.38 29.5,15.88 28,15.88 28,14.38 29.5,14.38 33,16.38 33,12.38 31.62,9.25 27,1.38 25,1.38 23,1.38 21,1.38 19,1.38 17,1.38 15.25,25 13.5,27.88 13,23.88 22,28.5 22,30.5 22,32.5 21.75,34.5 20,30.5 20.75,33.5 20,28.5 18,30.5 1,23.5 1,26 1,28.5 1,31 3,28.5 3,26 3,23.5 30.38,18.88 16.3,3.15 7.15,12.32 7.15,10.68 5.38,10.68 6.25,12.3 5.38,9.68 5.38,8.68 5.38,7.67 5.38,6.67 5.38,12.93 4.38,13.07 3.38,13.07 2.38,13.07 1.38,13.07 0.38,13.07 6.25,12.93 20.57,4.95 28.5,5.25 30.5,12.85 30.5,10.85 22.38,10.32 23.5,12.88 11.75,22.5 10,13.12 10.75,13.12 18.88,24.5 5,2 6,2 55,29 56.5,27.5 55,27.5 55,26 56.5,26 56.5,24.5 55,24.5 55,23 56.5,23 53.5,23 53.5,24.5 53.5,26 53.5,27.5 52,27.5 52,26 52,24.5 52,23 50.5,23 50.5,24.5 50.5,26 50.5,27.5 49,27.5 49,26 49,24.5 49,23 47.5,23 47.5,24.5 47.5,26 47.5,27.5 46,27.5 46,26 46,24.5 46,23 44.5,27.5 44.5,26 55.5,37.5 25.7,17.18 6.38,20.57 15.4,4.85 15.4,5.4 17.25,4.7 21.62,8.28 21.62,8.78 22.38,9.68 18.12,22.65 18.62,23.15 20.68,19.3
  pour Route2 (isolate 0.254): 34,0 0,0 0,6.6 5.2,6.6 5.2,12.9 0,12.9 0,42 57,42 57,19.5 36.5,19.5 34,17
  pour Top (isolate 0.254): 57,42 0,42 0,14 5.5,14 5.5,6 0,6 0,0 34,0 34,8 33,8 33,11 34,12 34,17 36.62,19.5 57,19.5
  pour Route3 (isolate 0.254): 34,0 9.5,0 9.5,6.5 25,6.5 25.5,7 25.5,15.5 24.5,16.5 21,16.5 20.4,15.9 20.4,10.1 11.6,10.1 11.6,10.69 10.79,11.5 9.62,11.5 8.5,10.38 8.5,7.5 9,7 9,0 0,0 0,6.6 5.2,6.6 5.2,12.9 0,12.9 0,42 57,42 57,19.5 36.5,19.5 34,17
  pour Top (no thermals): 47.5,15.5 47.5,10.8 43.2,6.5 36,6.5 34,4.5 31.5,4.5 31.5,8.12 41,8.12 41,10.5 46,15.5
  pour Bottom (isolate 0.254): 57,42 0,42 0,0 13.5,0 13.5,5.9 8.35,5.9 7.4,6.85 7.4,14.75 8.88,16.1 9.65,16.1 10.6,15.15 10.6,10 19.9,10 19.9,11 21,11 21,19.25 20.35,19.9 17.45,19.9 16.4,20.95 16.4,21.55 17.35,22.5 21.25,22.5 24.1,19.65 24.1,12.15 24.6,11.65 24.6,5.85 23.65,4.9 22.48,4.9 21.5,5.88 14,5.85 14,0 34,0 34,8 33,8 33,11 34,12 34,17 36.62,19.5 57,19.5
  pour Top (no thermals): 0,14 0,9.9 1.3,9.9 1.3,12.8 5.1,12.8 5.1,6.7 0,6.7 0,6 5.5,6 5.5,14
I1+
  Top 0.305: U1.3 41,31.89 C9.1
  Top 0.406: R9.1 45.3,31.85 C8.1 43.2,32.15 C9.1
I1-
  Top 0.305: U1.4 38.97,32.53 40.28,33.85 C9.2
  Top 0.406: R10.1 45.3,34.15 C10.2 43.2,33.85 C9.2
LDO_IN  (via drill 0.2)
  Top 0.254: 19.99,10 U2.48 20.64,10.21 v20.65,10.2 20.85,10 C17.1 | U2.36 14,9.5 v12.45,7.95 | U2.25 C26.1 9.75,14.72 9.35,15.12 v9.12,15.12 | 9,6.15 v9,7.12 | C28.1 11.5,5.85 | 12.6,5.65 L8.P$2
  Top 0.406: 9,6.15 9.3,5.85 C27.1 C28.1 | 11.5,5.85 11.7,5.65 12.6,5.65
  pour Bottom (isolate 0.254): 8,14.5 9,15.5 9.5,15.5 10,15 10,9 16,9 16.5,8.5 17.5,8.5 18.4,9.4 20.5,9.4 20.5,10.4 21.28,10.4 21.5,10.18 21.5,6.4 14.2,6.4 14.2,6.5 8.5,6.5 8,7
LED1
  Top 0.254: U2.1 19.99,19.99 20.5,20.5 LED1.C
LED2
  Top 0.254: U2.2 19.49,20.26 20.79,21.55 LED2.C
LIN  (via drill 0.46, 0.7)
  Top 1.422: v71.5,18 71.5,3 70.5,2 D6.A
  Top 2.54: R6.2 103.5,18.92 L_IN.P$3
  Route3 1.422: v71.5,18 L_IN.P$3
  Bottom 0.61: v71.5,18 65,18 61,22 61,28 58.85,30.15 R2.1
  other vias: 100,7.5 101,7.5 101,6.5 100,6.5 100,5.5 101,5.5 101,4.5 100,4.5
  pour Top (no thermals): 99.5,3.5 99.5,15.5 98.5,16.5 98.5,18 108.5,18 108.5,16.5 104,12 104,5.5 102,3.5
  pour Bottom (no thermals): 99.5,3.5 99.5,15.5 98.5,16.5 98.5,18 108.5,18 108.5,16.5 104,12 104,5.5 102,3.5
LOUT  (via drill 0.46)
  other vias: 77.5,15.5 76.5,15.5 76.5,14.5 77.5,14.5 76.5,13.5 81.5,16.5 82.5,15.5 81.5,15.5 80.5,15.5 79.5,15.5 78.5,15.5 76.5,16.5 77.5,16.5 78.5,16.5 79.5,16.5 80.5,16.5 95,4.5 96,4.5 96,5.5 95,5.5 95,6.5 96,6.5 96,7.5 95,7.5 82.5,16.5 77.5,13.5 77.5,12.5 76.5,12.5 76.5,11.5 77.5,11.5 77.5,10.5 76.5,10.5 78.5,10.5 78.5,11.5 79.5,11.5 79.5,10.5 80.5,10.5 80.5,11.5 81.5,11.5 81.5,10.5 82.5,10.5 82.5,11.5 82.5,12.5 81.5,12.5 81.5,13.5 82.5,13.5 82.5,14.5 81.5,14.5
  pour Top (no thermals): 96.5,4 78.83,4 76,6.83 76,18 83,18 83,10 96.5,10
  pour Bottom (no thermals): 96.5,4 78.83,4 76,6.83 76,18 83,18 83,10 96.5,10
MAIN_GROUND
  Top 3.81: GROUNDOUT.B3,0 GND_IN.P$1
  Bottom 3.81: GROUNDOUT.B3,0 GND_IN.P$1
MSP_CLK
  Top 0.254: U2.5 17.99,19.89 25,26.9 25,33 26.48,34.48 U1.22
MSP_CS
  Top 0.254: U1.21 24.76,35.13 23.5,33.88 23.5,27.05 16.5,20.1 U2.8
MSP_INTR  (via drill 0.2)
  Top 0.254: U2.15 12.99,20.01 v12.5,20.5 | U1.26 v26.89,31.89 v26.88,31.88
  Bottom 0.254: v12.5,20.5 14.5,22.5 17,22.5 18.25,23.75 19.2,23.75 26.88,31.43 v26.88,31.88
MSP_MISO  (via drill 0.2)
  Top 0.254: U2.6 17.44,19.89 24.5,26.95 24.5,33.23 v25.15,33.88 | U1.23 26.69,33.84 v26.6,33.88
  Bottom 0.254: v25.15,33.88 v26.6,33.88
MSP_MOSI  (via drill 0.2)
  Top 0.254: U2.7 16.99,19.99 24,27 24,33.5 v24.4,33.9 | U1.24 26.43,33.19 v26.38,33.12
  Bottom 0.254: v26.38,33.12 25.18,33.12 v24.4,33.9
N$1
  Top 0.254: U2.40 15.99,9.51 16.1,9.4 16.1,7.6 16.3,7.4 L7.P$1
N$2
  Top 0.254: U2.41 16.49,7.91 17.5,6.9 17.5,5.7 17.8,5.4 L7.P$2
N$3
  Top 0.406: R10.2 47.5,34.5 L4.2
N$4
  Top 0.813: D6.C 65,2.02 | T1.1 61.71,2.27 D7.A
  Top 1.016: C34.+ 65.96,8.46 65,7.5 65,2.02
  Top 1.27: D6.C 62.02,2 D7.A
N$5
  Top 0.254: L8.P$1 13,7.2 13,7.7 13.65,8.35 14.5,8.35 14.99,8.84 U2.38
N$6
  Top 0.305: C35.2 FLT1.P$3
N$7
  Top 0.254: U3.7 17.62,25.73 R11.1
N$8
  Top 0.254: U3.3 11.46,24.5 10.88,24.5 10.62,24.75 10.62,26 11,26.38 14.88,26.38 15.5,27 15.5,27.35 R12.1
  Top 0.305: U3.3 11.54,24.5
N$9  (via drill 0.2)
  Top 0.305: K1.+ 108.33,4.33 105.5,1.5 v75,1.5 | v59,19 56,22 43.65,22 R13.1
  Route2 0.254: v75,1.5 70,6.5 70,17 68,19 v59,19
N$10  (via drill 0.2)
  Top 0.305: K1.- 110.87,4.87 106.5,0.5 v75,0.5 | Q1.2 39.5,22.95 39.5,21.5 40,21 56,21 v58.5,18.5
  Route2 0.254: v75,0.5 69.25,6.25 69.25,17 67.75,18.5 v58.5,18.5
N$11
  Top 0.305: FLT1.P$1 C33.1
N$12
  Top 0.254: U2.35 13.5,9.62 12.38,8.5 11.63,8.5 R25.2 10.51,8.51 TP2.TP
N$13
  Top 0.305: R14.1 39.2,25.15 Q1.1
N$14
  Top 0.254: U2.34 13,9.78 12.17,8.95 TP1.TP R26.2
N$15
  Top 0.254: U2.21 11.12,16.51 9.45,18.18 9.45,19.26 8.86,19.84 R34.2 8.13,19.84 R27.1
N$16
  Top 0.254: U2.62 21.43,17.51 TP4.TP
N$17  (via drill 0.7)
  Top 1.27: D7.C v62,8
  Bottom 1.27: v62,8 D7.C
N$18
  pour Bottom (no thermals): 42.5,5.5 41.5,5.5 40.5,4.5 37.5,4.5 37,4 37,1 37.5,0.5 42.5,0.5 43,1 43,5
N$19
  Top 0.254: LED1.A R16.1
N$20
  Top 0.254: LED2.A R17.1
N$21
  Top 0.406: U4.4 60.05,9.9 R19.2
N$22
  Top 0.61: T1.2 53.62,4.75 53.88,5.01 U4.8
  Bottom 0.813: D8.A 52.84,1.98 T1.2
N$23  (via drill 0.2)
  Top 0.406: U4.6 53.13,8.63 v53,8.5
  Route3 0.813: C39.+ 51.5,14.54 51.5,10 v53,8.5
  Bottom 0.406: v53,8.5 C38.1
  Bottom 0.61: D9.C 53.25,7.1 53,7.35 v53,8.5
N$24  (via drill 0.2)
  Top 0.406: U4.5 53.1,9.9 v53,10
  Bottom 0.406: v53,10 R20.2
  Bottom 0.61: v53,10 53,10.1 52.75,10.35 R21.1
N$25
  Bottom 0.61: R22.1 51.75,4.9 D9.A
N$26
  Bottom 0.61: R21.2 R22.2 50.32,6.85 50.06,7.1 T1.3
N$30
  Top 0.254: U2.52 R28.1
N$31
  Top 0.254: R29.1 14.76,2.5 CC_RESET.1
N$32
  Bottom 0.406: R5.1 R7.2 R4.2
N$35
  Top 0.305: C4.2 33.85,39.24 U1.14
N$39
  Bottom 0.406: R2.2 R3.1
N$42
  Top 0.406: L3.2 47.35,29.9 R9.2
N$130
  Top 0.406: MSP430JTAG.4 7.42,39.27 PWR_SEL.3
NEUTRAL_IN  (via drill 0.4, 0.46, 0.7)
  Top 0.254: N_IN.P$3 104.42,29.08 104.5,29.08 | L3.1 49.5,29.5 | 52.55,30.25 52.75,30.25
  Top 0.406: 52.55,30.25 D3.2 50.3,30.3 49.5,29.5
  Top 0.61: 52.7,30.5 D3.2 58.2,30.3 59.5,29 89.5,29 91,30.5 91,33.5 93,35.5 v94,35.5
  Top 2.54: 103.5,29.08 104.5,29.08 R6.1
  Route3 1.27: v68.5,36 72.5,40 97.5,40 103.5,34 N_IN.P$3
  Route3 1.422: 67,14 C34.- 60.5,20.04 60.5,28 v68.5,36
  Bottom 0.406: N_IN.P$3 105.5,30
  Bottom 0.61: 68.44,35.94 v68.5,36 R30.1
  Bottom 0.813: C38.2 R20.1 v57.35,11.25
  Bottom 1.016: R24.1 48.7,11.1 T1.4
  other vias: 94,37.5 95,37.5 96,37.5 97,37.5 97,36.5 97,35.5 97,34.5 97,33.5 97,32.5 96,32.5 95,32.5 94,32.5 94,33.5 94,34.5 94,36.5
  pour Top (no thermals): 67.5,14.5 60.5,14.5 60,14 49,14 49,9.5 49.5,9 51,9 52.5,10.5 55.5,10.5 58,8.5 58,6 60.5,6 60.5,8 64.5,12 67,12 68,13 68,14
  pour Top (no thermals): 93.5,38 102.8,38 108.5,32.3 108.5,30 98.5,30 98.5,31 97.5,32 93.5,32
  pour Bottom (no thermals): 93.5,38 102.84,38 108.5,32.34 108.5,30 98.5,30 98.5,31 97.5,32 93.5,32
NEUTRAL_OUT  (via drill 0.46)
  Top 0.406: D3.1 50,35.5 L4.1
  Top 0.61: v58,33 55.5,35.5 D3.1
  Route2 0.61: v88,35.5 89,35.5 91,33.5 91,30.5 89.5,29 62,29 v58,33
  other vias: 82.5,36.5 82.5,34.5 82.5,37.5 82.5,35.5 82.5,33.5 82.5,32.5 82.5,31.5 82.5,30.5 81.5,30.5 81.5,31.5 81.5,32.5 81.5,33.5 81.5,34.5 81.5,35.5 81.5,36.5 81.5,37.5 80.5,37.5 77.5,37.5 78.5,37.5 79.5,37.5 76.5,37.5 76.5,36.5 80.5,31.5 80.5,30.5 79.5,30.5 79.5,31.5 76.5,35.5 76.5,34.5 78.5,31.5 78.5,30.5 77.5,30.5 77.5,31.5 76.5,33.5 76.5,32.5 76.5,31.5 76.5,30.5 85,37.5 85,36.5 85,35.5 85,34.5 85,33.5 85,32.5 86,32.5 87,32.5 88,32.5 88,33.5 88,34.5 88,36.5 88,37.5 87,37.5 86,37.5 80.5,36.5 79.5,36.5 78.5,36.5 77.5,36.5 77.5,35.5 77.5,34.5 77.5,33.5 77.5,32.5
  pour Bottom (no thermals): 76,38 88.5,38 88.5,30 76,30
  pour Top (no thermals): 76,38 88.5,38 88.5,30 76,30
RELAY_CTL
  Top 0.305: U1.27 30.77,31.23 35,27 37.35,27 R14.2
RELAY_IO
  Top 0.254: U2.64 26,18.5 27,19.5 27,22.5 25.5,24 25.5,31.5 26.54,32.53 U1.25
RST  (via drill 0.2)
  Top 0.254: v21.5,36.75 21.5,36.25 18.25,33 16.31,33 MSP430JTAG.11 | U1.15 26.96,39.03 v26.5,39.5 26.15,39.85 R1.2
  Bottom 0.254: v21.5,36.75 24.25,39.5 v26.5,39.5
RTC_XTAL
  Top 0.254: U2.51 26.15,12.01 OCS1.OUT
TCK
  Top 0.254: 26.27,37.73 20.73,37.73 18.5,35.5 11.27,35.5 MSP430JTAG.7
  Top 0.305: 26.27,37.73 U1.17
TDI  (via drill 0.2)
  Top 0.254: 24.21,36.44 23.43,36.44 v23,36
  Top 0.305: 24.21,36.44 U1.19
  Bottom 0.254: v23,36 22.5,35.5 6.19,35.5 MSP430JTAG.3
TDO  (via drill 0.2)
  Top 0.254: 25.32,35.78 24.29,35.78 v24,35.5
  Top 0.305: 25.32,35.78 U1.20
  Bottom 0.254: v24,35.5 21,32.5 4.11,32.5 MSP430JTAG.1
TEST
  Top 0.254: 26.86,38.38 11.62,38.38 MSP430JTAG.8
  Top 0.305: 26.86,38.38 U1.16
TMS
  Top 0.254: 25.11,37.09 23.09,37.09 18.5,32.5 9.19,32.5 MSP430JTAG.5
  Top 0.305: 25.11,37.09 U1.18
V1
  Bottom 0.406: R4.1 R3.2
V1+  (via drill 0.5)
  Top 0.305: U1.1 34.41,30.59 v36,29
  Bottom 0.406: R5.2 C5.1 45.85,30.15 45,31 45,32 | 45,32 C6.1 | 45,32 44,32 43.5,31.5 43.5,30 42.5,29 v36,29
V1-  (via drill 0.5)
  Top 0.305: U1.2 35.77,31.23 v37,30
  Bottom 0.406: R8.1 C7.2 45.61,35.85 45,35.24 C6.2 43.35,33.85 42.5,33 42.5,31 41.5,30 v37,30
VCC  (via drill 0.2, 0.3, 0.4, 0.6)
  Top 0.254: U2.39 v15.5,8.5 15.5,7.75 C32.1 C31.1 | 21.5,13.51 21.74,13.51 C30.1 22.25,13.25 v22.65,12.85 22.5,12.5 R28.2 | 21.5,13.51 U2.54 | U2.10 15.49,20.24 C29.1 v16,21.25 | U2.44 18,9 v18.25,8.75 18.5,8.5 C13.1 U2.47 | R15.2 9.95,10.95 v9.5,10.5 | C11.1 U3.8 | v29.5,41 R1.1 | R18.1 7.46,21.75 v8.35,20.85 8.35,20.75 R34.1 | U2.37 14.49,9.21 v14.2,8.9 | v17.88,28 16.73,29.15 R12.2 15.35,28.5 13,28.5 12.55,28.05 R33.2 | R31.2 21.52,13.49 21.5,13.51
  Top 0.305: 34.62,38.38 U1.13
  Top 0.406: v20,25.5 R11.2 | C11.1 17.85,27.98 v17.88,28 | R13.2 43.5,25 43,25.5 41.5,25.5 41,26 v41,27.5 | 34.62,38.38 35.5,37.5 C3.2 C1.2 36.15,40.39 36.74,40.98 v40.5,40.98
  Top 0.61: OCS1.VCC 26.35,7.15 C36.1 v25,5 | R16.2 R17.2 v26,21.55
  Top 0.813: C41.1 38.55,9.45 | C42.1 36.4,9.35 R23.2 | 39.5,13.5 v39,13.5 39.5,14
  Route2 0.813: v41,27.5 40.5,28 v40.5,40.98
  Route3 0.254: v20,25.5 18,25.5 15.5,23 10.5,23 v8.35,20.85
  Route3 0.305: v20,25.5 19,25.5 17.5,24 17.5,22.75 v16,21.25
  Route3 0.406: v20,25.5 20,25.88 v17.88,28
  Route3 0.61: v26,21.55 26,22 22.5,25.5 v20,25.5
  Route3 0.813: v26,21.55 25,21.5
  Route3 1.016: v25,5 25,7 24,8 | 25,21.5 25,20 24,19 24,15.9
  Bottom 0.305: v29.5,41 40.48,41 v40.5,40.98
  Bottom 0.406: PWR_SEL.2 6.88,38 9,38 12,41 v29.5,41
  Bottom 0.813: v41,27.5 v41,14 | PWR.1 35.16,9.66 v39,13.5
  Bottom 1.016: D10.C v39,13.5 34,13.5 v26,21.55
  pour Route3 (isolate 0.254): 10.6,10.9 11,10.5 11,9.95 11.45,9.5 20.6,9.5 21,9.95 21,15.5 21.4,15.9 24.35,15.9 24.9,15.35 24.9,7.6 24.5,7.1 9.65,7.1 9.1,7.65 9.1,10.19 9.81,10.9
  pour Top (no thermals): 44.5,15 44.5,16.5 44,17 42,17 36,11 34,11 33.5,10.5 33.5,8.75 40.25,8.75 40.25,10.75
VDD_DIG  (via drill 0.2)
  Top 0.254: U2.56 22.26,14.51 C20.1 22.55,15.35 22.7,15.5 22.75,15.5 | 22.75,15.5 C19.1 | 22.75,15.5 v22.82,15.57 | L5.P$1 v23,5.9 | U2.9 16,20.5 16.55,21.05 C12.1 16.95,21.25 v17.23,21.52
  Route2 0.254: 22.25,15 23,15.5 22.9,15.5 v22.82,15.57
  pour Bottom (isolate 0.254): 17.5,21.9 17,21.4 17,21.1 17.6,20.5 20.5,20.5 21.6,19.4 21.6,10.9 22.1,10.4 22.1,6 22.6,5.5 23.5,5.5 24,6 24,11.5 23.5,12 23.5,19.5 21.1,21.9
VDD_PLL
  Top 0.254: C16.1 10.69,15.01 U2.24
VDD_RAM
  Top 0.254: U2.49
VREF
  Top 0.305: U1.9 34.72,35.78 35,35.5 C2.1
WLAN_XTALN
  Top 0.254: U2.22 10.99,16.01 9,18 9,18.7 8.5,19.2 7.2,19.2 6.5,18.5 6.5,17.8 XT1.3 6.55,17.75 C15.1
WLAN_XTALP
  Top 0.254: U2.23 10.87,15.51 10,16.38 8,16.38
  Top 0.305: C14.1 7.65,16 XT1.1 8,16.38

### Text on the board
tPlace: TI WiFi SmartPlug | B. Basile / Aug 2013 | GND | GND | VCC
